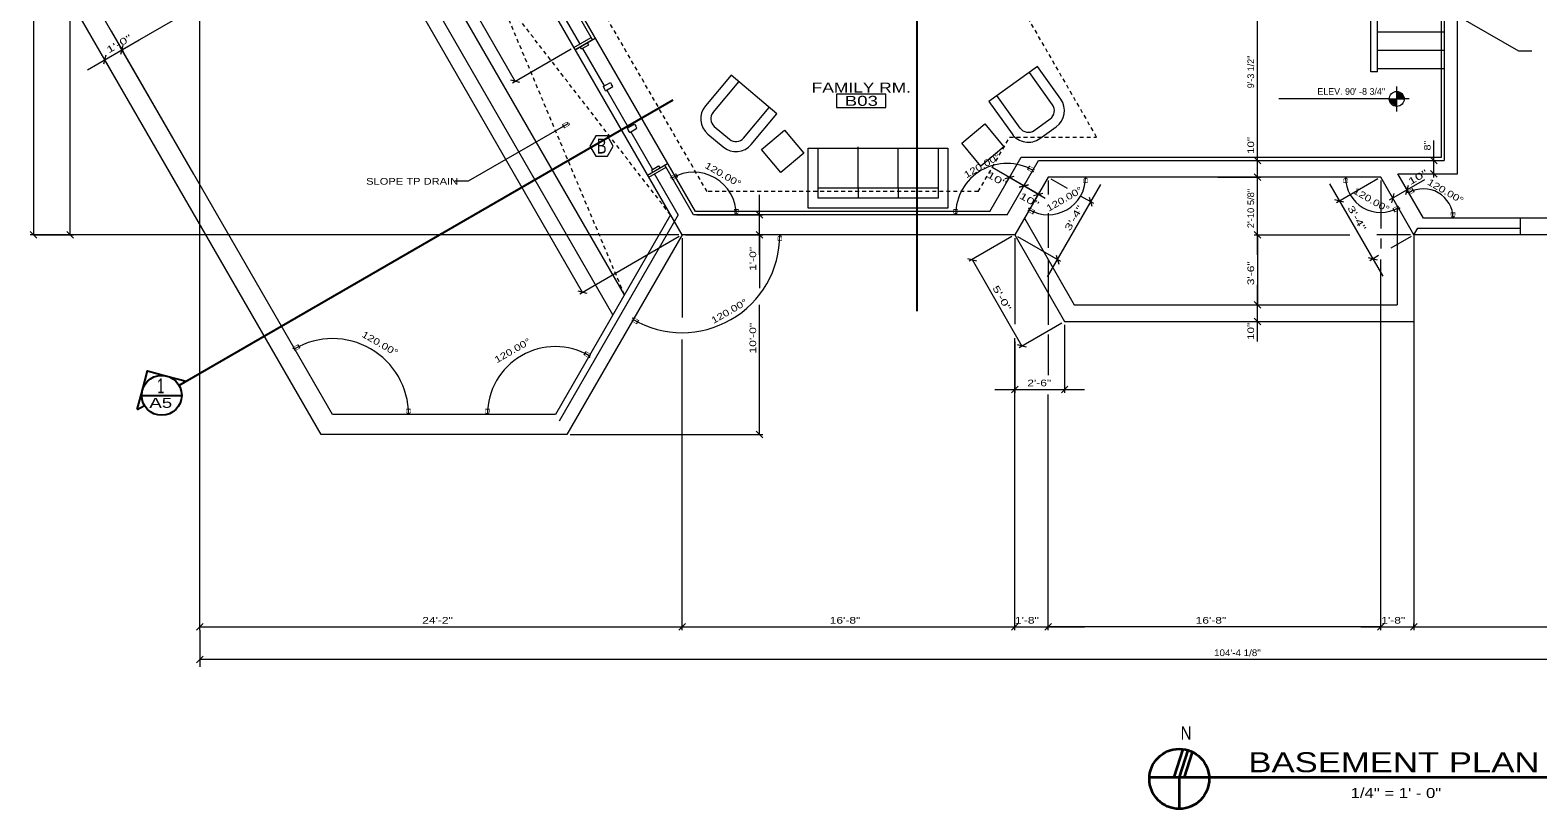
# Model space of a CAD drawing. Extents: x 7 to 126, y 6 to 93.
# Drawn here: x 8.2 to 83.7, y 5.6 to 44.6 of the extents above; entities that cross this region are included whole.
import ezdxf
from ezdxf.enums import TextEntityAlignment as Align

# ---------------------------------------------------------------- set-up
doc = ezdxf.new("R2010")
doc.units = 0
doc.header["$LTSCALE"] = 0.13
doc.linetypes.add('SHORT_DASHED', pattern=[2.7, 1.5, -1.2])
for name, color, linetype, lineweight in [('13', 7, 'Continuous', 13), ('14', 7, 'Continuous', 13), ('15', 7, 'Continuous', 13), ('16', 7, 'Continuous', 13), ('20', 7, 'Continuous', 13), ('22', 7, 'SHORT_DASHED', 13), ('24', 7, 'Continuous', 13), ('34', 7, 'Continuous', 13), ('4', 7, 'Continuous', 13), ('40', 7, 'Continuous', 13), ('42', 7, 'Continuous', 13), ('44', 7, 'Continuous', 13), ('45', 7, 'Continuous', 13), ('47', 7, 'Continuous', 35), ('50', 7, 'Continuous', 13), ('6', 7, 'SHORT_DASHED', 13), ('7', 7, 'Continuous', 13)]:
    doc.layers.add(name, color=color, linetype=linetype, lineweight=lineweight)

msp = doc.modelspace()

# ---------------------------------------------------------------- linework, layer by layer
at = {"layer": '13'}
for p, q in [((28.9778, 55.6199), (35.7268, 43.9303)), ((40.6799, 35.3511), (39.4914, 37.4098)), ((40.6799, 35.3511), (34.714, 25.0178)), ((77.539, 34.3511), (77.7315, 34.6845)), ((77.7315, 34.6845), (82.8724, 34.6845))]:
    msp.add_line(p, q, dxfattribs=at)
at = {"layer": '14'}
msp.add_lwpolyline([(115.8724, 34.3511), (77.539, 34.3511), (75.8724, 37.2379), (59.2057, 37.2379), (57.539, 34.3511), (40.8724, 34.3511), (16.7057, 76.209), (22.539, 86.3127), (34.2057, 86.3127), (44.2057, 68.9922), (60.8724, 68.9922)], dxfattribs=at)
at = {"layer": '15'}
for p, q in [((79.0473, 62.3853), (79.0473, 38.0712)), ((79.7139, 37.4046), (79.7139, 56.3207)), ((36.3842, 44.1248), (34.6032, 47.2098)), ((35.4556, 43.733), (36.3216, 44.233)), ((39.2056, 37.2378), (40.0716, 37.7378)), ((76.7384, 37.4046), (79.7139, 37.4046)), ((76.7057, 35.7945), (76.7057, 30.8544)), ((82.8724, 34.3511), (82.8724, 35.1845)), ((77.539, 34.3511), (77.539, 30.021))]:
    msp.add_line(p, q, dxfattribs=at)
for points in [[(57.1541, 35.3511), (41.4497, 35.3511), (40.0092, 37.8461)], [(57.1541, 35.3511), (58.7246, 38.0712), (79.0473, 38.0712)], [(115.258, 35.1845), (78.0202, 35.1845), (76.7384, 37.4046)], [(58.0202, 35.1845), (60.5202, 30.8544), (76.7057, 30.8544)], [(57.539, 34.3511), (60.039, 30.021), (77.539, 30.021)]]:
    msp.add_lwpolyline(points, dxfattribs=at)
at = {"layer": '16'}
for p, q in [((35.5181, 43.6248), (36.5157, 44.2008)), ((35.5542, 43.6456), (36.4203, 44.1456)), ((35.8332, 43.6624), (36.1941, 43.8707)), ((36.1941, 43.8707), (36.1339, 43.975)), ((35.8332, 43.6624), (35.773, 43.7667)), ((35.8874, 43.6936), (36.9754, 41.809)), ((36.9213, 41.7778), (37.2821, 41.9861)), ((36.9213, 41.7778), (36.9815, 41.6735)), ((37.0417, 41.5692), (36.9815, 41.6735)), ((37.0417, 41.5692), (37.4026, 41.7775)), ((37.0959, 41.6004), (38.1813, 39.7204)), ((37.2821, 41.9861), (37.3423, 41.8818)), ((37.4026, 41.7775), (37.3423, 41.8818)), ((38.1272, 39.6891), (38.488, 39.8974)), ((38.1272, 39.6891), (38.1874, 39.5848)), ((38.2476, 39.4805), (38.1874, 39.5848)), ((38.2476, 39.4805), (38.6085, 39.6888)), ((38.3017, 39.5118), (39.3874, 37.6314)), ((38.488, 39.8974), (38.5482, 39.7931)), ((38.6085, 39.6888), (38.5482, 39.7931)), ((39.1431, 37.3461), (40.1408, 37.9221)), ((39.1792, 37.3669), (40.0452, 37.8669)), ((39.3332, 37.6002), (39.6941, 37.8085)), ((39.6941, 37.8085), (39.7543, 37.7042)), ((39.3332, 37.6002), (39.3934, 37.4959))]:
    msp.add_line(p, q, dxfattribs=at)
at = {"layer": '20'}
for p, q in [((75.7139, 44.5146), (79.0473, 44.5146)), ((75.7139, 43.5979), (79.0473, 43.5979)), ((75.7139, 42.6813), (79.0473, 42.6813))]:
    msp.add_line(p, q, dxfattribs=at)
at = {"layer": '22'}
msp.add_line((55.0345, 50.6771), (61.6389, 39.2379), dxfattribs=at)
for points in [[(55.7108, 36.5178), (42.1233, 36.5178), (28.8321, 59.5389)], [(55.7108, 36.5178), (57.2812, 39.2379), (61.6389, 39.2379)]]:
    msp.add_lwpolyline(points, dxfattribs=at)
at = {"layer": '24'}
for p, q in [((78.9223, 38.2379), (78.9223, 56.4583)), ((75.7139, 42.5146), (75.7139, 47.375)), ((56.2881, 35.5178), (57.8586, 38.2379)), ((57.8586, 38.2379), (78.9223, 38.2379))]:
    msp.add_line(p, q, dxfattribs=at)
for points in [[(56.2881, 35.5178), (41.5459, 35.5178), (29.6995, 56.0365)], [(75.7139, 42.5146), (75.3806, 42.5146), (75.3806, 47.375)]]:
    msp.add_lwpolyline(points, dxfattribs=at)
at = {"layer": '34'}
for p, q in [((59.4352, 40.8627), (58.2727, 42.4902)), ((42.4223, 40.4888), (43.7081, 42.0206)), ((57.8077, 39.7002), (56.6453, 41.3277)), ((43.9541, 39.2029), (45.24, 40.7347)), ((58.5052, 39.584), (59.319, 40.1652)), ((42.1623, 39.4014), (42.9282, 38.7584)), ((42.4838, 39.7843), (43.2497, 39.1414)), ((58.7959, 39.1771), (59.6096, 39.7583)), ((49.6935, 36.6904), (49.6934, 38.7574)), ((51.6935, 36.6904), (51.6934, 38.7049)), ((53.6934, 36.6904), (47.6934, 36.6904)), ((49.6935, 36.6904), (49.6935, 36.2036)), ((51.6935, 36.6904), (51.6934, 36.1896))]:
    msp.add_line(p, q, dxfattribs=at)
for points in [[(44.3371, 38.8814), (45.6229, 40.4133), (43.3252, 42.3421), (42.0393, 40.8102)], [(59.8421, 41.1533), (58.6796, 42.7808), (56.2384, 41.0371), (57.4009, 39.4096)], [(53.6934, 38.6904), (53.6934, 36.1905), (47.6934, 36.1904), (47.6934, 38.6904)]]:
    msp.add_lwpolyline(points, dxfattribs=at)
for points in [[(46.97, 38.4414), (45.8177, 37.4811), (44.8574, 38.6335), (46.0097, 39.5937)], [(56.9948, 38.7579), (55.8425, 37.7976), (54.8822, 38.9499), (56.0346, 39.9102)], [(54.1934, 35.6904), (47.1934, 35.6904), (47.1934, 38.6904), (54.1934, 38.6905)]]:
    msp.add_lwpolyline(points, close=True, dxfattribs=at)
for centre, radius, start, end in [((42.8052, 40.1673), 1, 139.98937, 229.98937), ((59.0284, 40.5721), 0.5, 305.5378, 35.5378), ((59.0284, 40.5721), 1, 305.5378, 35.5378), ((42.8052, 40.1673), 0.5, 139.98937, 229.98937), ((58.2146, 39.9908), 1, 215.5378, 305.5378), ((58.2146, 39.9908), 0.5, 215.5378, 305.5378), ((43.5712, 39.5244), 1, 229.98937, 319.98937), ((43.5712, 39.5244), 0.5, 229.98937, 319.98937)]:
    msp.add_arc(centre, radius, start, end, dxfattribs=at)
at = {"layer": '4'}
for p, q in [((37.9856, 31.3511), (15.2614, 70.7105)), ((37.4082, 30.3511), (15.5393, 68.2293)), ((23.3594, 25.3511), (9.6233, 49.1428)), ((22.7821, 24.3511), (8.5387, 49.0213)), ((40.295, 35.3511), (34.5215, 25.3511)), ((40.8724, 34.3511), (35.0989, 24.3511)), ((34.5215, 25.3511), (23.3594, 25.3511)), ((35.0989, 24.3511), (22.7821, 24.3511))]:
    msp.add_line(p, q, dxfattribs=at)
at = {"layer": '40', "lineweight": 25}
for p, q in [((52.6458, 30.5373), (52.6458, 54.1771)), ((15.6657, 26.8165), (40.4229, 41.1101)), ((15.0585, 27.2824), (16.0244, 27.0236)), ((13.5749, 25.6094), (13.8337, 26.5753)), ((15.6657, 26.8165), (16.0244, 27.0236)), ((13.5749, 25.6094), (13.9336, 25.8165)), ((13.7996, 26.3165), (15.7996, 26.3165))]:
    msp.add_line(p, q, dxfattribs=at)
msp.add_lwpolyline([(13.8337, 26.5753), (14.0925, 27.5412), (15.0585, 27.2824)], dxfattribs=at)
msp.add_circle((14.7996, 26.3165), 1, dxfattribs=at)
at = {"layer": '42'}
msp.add_lwpolyline([(37.4229, 38.8023), (37.1312, 39.3074), (36.5479, 39.3074), (36.2562, 38.8023), (36.5479, 38.2971), (37.1312, 38.2971)], close=True, dxfattribs=at)
at = {"layer": '44'}
for p, q in [((76.6783, 41.5342), (76.6783, 41.7842)), ((76.3033, 41.1594), (70.7616, 41.1594)), ((76.3036, 41.1594), (76.0536, 41.1594)), ((76.6783, 41.1594), (76.3049, 41.1296)), ((76.6783, 41.1594), (76.3113, 41.083)), ((76.6783, 41.1594), (76.323, 41.0401)), ((76.6783, 41.1594), (76.3395, 40.9995)), ((76.6783, 41.1594), (76.3657, 40.9532)), ((76.6783, 41.1594), (76.3977, 40.911)), ((76.6783, 41.1594), (76.4368, 40.8732)), ((76.6783, 41.1594), (76.4899, 40.8353)), ((76.6783, 41.1594), (76.5403, 40.8167)), ((76.6783, 41.1594), (76.6103, 40.7911)), ((76.6783, 41.1594), (76.7263, 41.531)), ((76.6783, 41.1594), (76.7837, 41.5189)), ((76.6783, 41.1594), (76.8252, 41.5042)), ((76.6783, 41.1594), (76.8761, 41.4775)), ((76.6783, 41.1594), (76.9247, 41.4418)), ((76.6783, 41.1594), (76.9588, 41.4081)), ((76.6783, 41.1594), (76.9852, 41.3745)), ((76.6783, 41.1594), (77.0079, 41.3374)), ((76.6783, 41.1594), (77.0237, 41.3047)), ((76.6783, 41.1594), (77.0365, 41.2694)), ((76.6783, 41.1594), (77.045, 41.2381)), ((76.6783, 41.1594), (77.0508, 41.2014)), ((76.6783, 41.1594), (77.0531, 41.1594)), ((76.6783, 40.7847), (76.6783, 41.1594)), ((77.3031, 41.1594), (77.0531, 41.1594)), ((76.6783, 40.5347), (76.6783, 40.7847))]:
    msp.add_line(p, q, dxfattribs=at)
msp.add_lwpolyline([(76.3036, 41.1594), (76.6783, 41.1594), (76.6783, 41.5342)], dxfattribs=at)
msp.add_circle((76.6783, 41.1594), 0.375, dxfattribs=at)
at = {"layer": '45'}
msp.add_lwpolyline([(48.6026, 40.7271), (51.0878, 40.7271), (51.0878, 41.3977), (48.6026, 41.3977)], close=True, dxfattribs=at)
at = {"layer": '47'}
for p, q in [((65.5261, 7.195), (65.973, 8.5995)), ((65.7885, 7.195), (66.2187, 8.5469)), ((66.0508, 7.195), (66.4515, 8.4543)), ((64.285, 7.195), (84.1994, 7.195)), ((65.7827, 7.195), (65.7827, 5.6116))]:
    msp.add_line(p, q, dxfattribs=at)
msp.add_circle((65.7827, 7.1116), 1.5, dxfattribs=at)
at = {"layer": '50'}
for p, q in [((8.375, 86.3127), (8.375, 34.3511)), ((35.8878, 31.4733), (18.5561, 61.4926)), ((10.2188, 34.3511), (10.2188, 57.2579)), ((16.7057, 14.5521), (16.7057, 56.3333)), ((27.0989, 51.4175), (32.5155, 42.0356)), ((12.8094, 43.6243), (25.5111, 50.9576)), ((69.6979, 38.0712), (69.6979, 47.3596)), ((11.0773, 42.6243), (13.6754, 44.1243)), ((12.2692, 44.56), (12.8927, 43.48)), ((12.7484, 43.3966), (12.8704, 43.852)), ((12.7484, 43.3966), (12.8704, 43.852)), ((12.7484, 43.3966), (12.8704, 43.852)), ((15.5771, 36.8306), (11.86, 43.2686)), ((12.0044, 43.352), (11.8824, 42.8966)), ((16.408, 37.3913), (12.7261, 43.7686)), ((35.3113, 43.6497), (32.3712, 41.9522)), ((32.7432, 41.9746), (32.2879, 42.0966)), ((69.6979, 36.2379), (69.6979, 39.0712)), ((78.5417, 37.2188), (78.5417, 39.0729)), ((69.0526, 38.0712), (69.8646, 38.0712)), ((69.8646, 37.9046), (69.5312, 38.2379)), ((69.8646, 37.9046), (69.5312, 38.2379)), ((69.6979, 33.3511), (69.6979, 38.2379)), ((78.7083, 37.9062), (78.375, 38.2396)), ((78.5938, 38.0729), (78.7083, 38.0729)), ((58.8582, 36.3026), (56.4045, 37.7193)), ((57.4981, 37.2803), (57.0428, 37.1583)), ((59.0677, 36.1817), (57.1261, 37.3026)), ((57.1741, 37.0523), (57.3538, 37.3637)), ((59.2057, 37.0712), (59.2057, 36.375)), ((59.35, 37.1546), (60.1594, 36.6873)), ((67.7057, 37.2379), (69.8646, 37.2379)), ((69.8646, 37.0712), (69.5312, 37.4046)), ((69.5312, 37.4046), (69.8646, 37.0712)), ((75.728, 37.1546), (73.661, 35.9611)), ((75.8724, 37.0712), (75.8724, 34.6771)), ((78.0653, 37.1063), (76.3041, 36.0895)), ((78.375, 37.5712), (78.7083, 37.2379)), ((78.3928, 37.4046), (78.7083, 37.4046)), ((44.75, 33.3511), (44.75, 36.3511)), ((57.7645, 36.7416), (58.2198, 36.8636)), ((58.2198, 36.8636), (57.7645, 36.7416)), ((58.0401, 36.8856), (58.0755, 36.947)), ((58.4731, 35.969), (58.7972, 36.5303)), ((58.4862, 36.325), (58.9415, 36.447)), ((59.1816, 32.2481), (61.8483, 36.8669)), ((61.4926, 35.9175), (60.8658, 36.2794)), ((73.3053, 36.9105), (75.972, 32.2917)), ((76.6337, 35.9193), (76.3942, 36.334)), ((76.5386, 36.4173), (76.4166, 35.962)), ((77.295, 36.4404), (77.1159, 36.7506)), ((77.1383, 36.3786), (77.2603, 36.834)), ((44.9167, 35.1845), (44.5833, 35.5178)), ((61.4093, 35.7732), (61.2873, 36.2285)), ((74.033, 35.9835), (73.5776, 36.1055)), ((41.6164, 35.3511), (44.9167, 35.3511)), ((59.2057, 35.4479), (59.2057, 33.7083)), ((8.5417, 34.1845), (8.2083, 34.5178)), ((40.7057, 34.3511), (8.2083, 34.3511)), ((8.375, 34.3511), (10.3854, 34.3511)), ((10.3854, 34.1845), (10.0521, 34.5178)), ((40.728, 34.2678), (35.7434, 31.3899)), ((40.8724, 34.1845), (40.8724, 30.2083)), ((41.039, 34.3511), (44.9167, 34.3511)), ((44.5833, 34.5178), (44.9167, 34.1845)), ((44.5833, 34.5178), (44.9167, 34.1845)), ((44.75, 34.3511), (44.75, 31.6875)), ((57.3947, 34.2678), (55.254, 33.0319)), ((57.539, 34.1845), (57.539, 29.8854)), ((57.6834, 34.2678), (59.826, 33.0308)), ((69.8646, 34.1845), (69.5312, 34.5178)), ((69.5312, 34.5178), (69.8646, 34.1845)), ((69.5312, 34.5178), (69.8646, 34.1845)), ((69.5312, 34.3511), (74.3333, 34.3511)), ((69.6979, 34.3511), (69.6979, 30.8544)), ((69.6979, 34.3511), (69.8646, 34.3511)), ((77.3724, 34.3511), (75.6875, 34.3511)), ((75.8724, 34.1667), (75.8724, 33.6667)), ((77.3947, 34.2678), (76.3776, 33.6806)), ((77.539, 34.1845), (77.539, 14.5521)), ((59.6206, 33.3418), (59.7426, 32.8864)), ((75.3276, 33.0744), (75.7709, 33.3303)), ((55.1707, 33.1762), (55.626, 33.0542)), ((55.3984, 33.1152), (57.8984, 28.7851)), ((59.2057, 33.0938), (59.2057, 29.8438)), ((75.2443, 33.2187), (75.6996, 33.0967)), ((75.8724, 14.5521), (75.8724, 33.125)), ((69.6979, 29.021), (69.6979, 31.8544)), ((36.1154, 31.4123), (35.6601, 31.5343)), ((69.8646, 30.6877), (69.5312, 31.021)), ((69.8646, 30.6877), (69.5312, 31.021)), ((44.75, 24.3511), (44.75, 30.8542)), ((68.7796, 30.8544), (69.8646, 30.8544)), ((59.8947, 29.9377), (57.754, 28.7018)), ((60.039, 29.8544), (60.039, 26.4375)), ((68.9557, 30.021), (69.8646, 30.021)), ((69.5312, 30.1877), (69.8646, 29.8544)), ((40.8724, 14.5521), (40.8724, 29.1146)), ((57.539, 14.5521), (57.539, 29.1875)), ((57.539, 29.0208), (57.539, 26.4375)), ((58.126, 28.7241), (57.6707, 28.8461)), ((59.2057, 29.3698), (59.2057, 27.3333)), ((56.539, 26.6042), (61.039, 26.6042)), ((57.7057, 26.7708), (57.3724, 26.4375)), ((59.8724, 26.4375), (60.2057, 26.7708)), ((59.2057, 14.5521), (59.2057, 26.3646)), ((35.2655, 24.3511), (44.9167, 24.3511)), ((44.9167, 24.1845), (44.5833, 24.5178)), ((16.539, 14.5521), (16.8724, 14.8854)), ((16.7057, 14.7188), (40.8724, 14.7188)), ((16.7057, 14.5521), (16.7057, 12.7188)), ((41.039, 14.8854), (40.7057, 14.5521)), ((40.7057, 14.5521), (41.039, 14.8854)), ((40.8724, 14.7188), (61.039, 14.7188)), ((56.539, 14.7188), (60.2057, 14.7188)), ((57.7057, 14.8854), (57.3724, 14.5521)), ((57.7057, 14.8854), (57.3724, 14.5521)), ((57.7057, 14.8854), (57.3724, 14.5521)), ((57.539, 14.7188), (57.539, 14.8854)), ((59.039, 14.5521), (59.3724, 14.8854)), ((59.039, 14.5521), (59.3724, 14.8854)), ((75.8724, 14.7188), (59.2057, 14.7188)), ((74.8724, 14.7188), (78.539, 14.7188)), ((76.039, 14.8854), (75.7057, 14.5521)), ((76.039, 14.8854), (75.7057, 14.5521)), ((77.3724, 14.5521), (77.7057, 14.8854)), ((77.3724, 14.5521), (77.7057, 14.8854)), ((77.3724, 14.5521), (77.7057, 14.8854)), ((77.539, 14.7188), (77.539, 14.8854)), ((77.539, 14.7188), (115.8724, 14.7188)), ((16.539, 12.9271), (16.8724, 13.2604)), ((16.7057, 13.4688), (16.7057, 12.9271)), ((121.0473, 13.0938), (16.7057, 13.0938))]:
    msp.add_line(p, q, dxfattribs=at)
for points in [[(77.4062, 46.6771), (82.7784, 43.5755), (83.4451, 43.5755)], [(35.1458, 39.9167), (30.1534, 37.0343), (29.4868, 37.0343)]]:
    msp.add_lwpolyline(points, dxfattribs=at)
for centre, radius, start, end in [((57.1541, 35.3511), 2.5802, 59.99997, 180), ((41.4497, 35.3511), 2.1384, 0, 119.99947), ((59.2057, 37.2379), 1.8804, 240.00002, 360), ((75.8724, 37.2379), 1.7622, 180, 300.00032), ((78.0202, 35.1845), 1.4771, 0, 119.9997), ((40.8724, 34.3511), 4.8961, 240.0001, 0), ((23.3594, 25.3511), 3.8058, 0, 119.99997), ((34.5215, 25.3511), 3.4038, 59.99988, 180)]:
    msp.add_arc(centre, radius, start, end, dxfattribs=at)
at = {"layer": '6'}
for p, q in [((37.9856, 31.3511), (31.6949, 46.3234)), ((40.295, 35.3511), (31.7616, 46.3759))]:
    msp.add_line(p, q, dxfattribs=at)
at = {"layer": '7'}
msp.add_lwpolyline([(115.8724, 34.3511), (77.539, 34.3511), (75.8724, 37.2379), (59.2057, 37.2379), (57.539, 34.3511), (40.8724, 34.3511), (16.7057, 76.209), (22.539, 86.3127), (34.2057, 86.3127), (44.2057, 68.9922), (60.8724, 68.9922), (64.2057, 63.2187), (65.039, 63.2187), (75.039, 63.2187), (80.039, 71.8789), (96.7057, 71.8789), (98.789, 75.4873), (113.4884, 75.4873), (121.0473, 51.0685)], dxfattribs=at)

# ---------------------------------------------------------------- texts
at = {"layer": '40'}
for s, height, width, p in [('1', 0.75, 0.65, (14.7559, 26.4175)), ('A5 ', 0.5, 1.4, (14.8819, 25.6915))]:
    msp.add_text(s, height=height, dxfattribs=dict(at, width=width)).set_placement(p, align=Align.CENTER)
at = {"layer": '42', "width": 0.75}
msp.add_text('B', height=0.75, dxfattribs=at).set_placement((36.8396, 38.4273), align=Align.CENTER)
at = {"layer": '44'}
msp.add_text('ELEV. 90\' -8 3/4"', height=0.3333, dxfattribs=at).set_placement((72.6991, 41.3678))
at = {"layer": '45'}
for s, width, p in [('     FAMILY RM.     ', 1.3, (49.8526, 41.481)), (' B03 ', 1.4, (49.8526, 40.8144))]:
    msp.add_text(s, height=0.5, dxfattribs=dict(at, width=width)).set_placement(p, align=Align.CENTER)
at = {"layer": '47'}
for s, height, width, p in [('N', 0.6667, 0.85, (65.8481, 9.0793)), ('BASEMENT PLAN', 1, 1.3, (69.241, 7.445)), ('1/4" = 1\' - 0"', 0.5, 1.25, (74.366, 6.1533))]:
    msp.add_text(s, height=height, dxfattribs=dict(at, width=width)).set_placement(p)
at = {"layer": '50'}
for s, rotation, width, p in [('1\'-0"', 30, 1.55, (12.1487, 43.4353)), ('10"', 90, 1.3, (69.5312, 38.4046)), ('8"', 90, 1.2, (78.375, 38.5786)), ('120.00°', 330, 1.3, (41.9753, 37.7303)), ('120.00°', 30, 1.3, (55.1146, 37.178)), ('10"', 330, 1.6, (56.1039, 37.269)), ('10"', 30, 1.6, (77.3612, 36.8409)), ('120.00°', 330, 1.3, (78.1725, 36.8979)), ('10"', 330, 1.6, (57.729, 36.2159)), ('120.00°', 30, 1.3, (59.2377, 35.5054)), ('2\'-10 5/8"', 90, 1.05, (69.5312, 34.6848)), ('120.00°', 330, 1.3, (74.457, 36.4552)), ('3\'-4"', 60, 1.55, (60.2996, 34.5178)), ('3\'-4"', 300, 1.55, (74.1932, 35.7059)), ('1\'-0"', 90, 1.35, (44.5833, 32.5511)), ('3\'-6"', 90, 1.35, (69.5312, 31.8311)), ('5\'-0"', 300, 1.55, (56.4069, 31.7018)), ('120.00°', 30, 1.3, (42.4498, 29.8896)), ('120.00°', 330, 1.3, (24.7861, 29.273)), ('10\'-0"', 90, 1.35, (44.5833, 28.4141)), ('10"', 90, 1.3, (69.5312, 29.0948)), ('120.00°', 30, 1.3, (31.5885, 27.9178))]:
    msp.add_text(s, height=0.3333, rotation=rotation, dxfattribs=dict(at, width=width)).set_placement(p)
msp.add_text('9\'-3 1/2"', height=0.3333, rotation=90, dxfattribs=at).set_placement((69.5312, 41.6944))
for rotation, width, p in [(30, 2.35, (35.3125, 39.8846)), (330, 2.35, (58.4998, 37.4253)), (209.999, 2.35, (40.2139, 37.2351)), (90, 1.7, (61.1972, 37.2379)), (90, 1.7, (74.2213, 37.2379)), (210, 2.35, (77.115, 36.4957)), (270, 1.7, (43.477, 35.3511)), (270, 1.7, (54.4628, 35.3511)), (150, 2.35, (58.2099, 35.7698)), (30, 2.35, (76.9201, 35.6797)), (270, 1.7, (79.3861, 35.1845)), (90, 1.7, (45.8796, 34.3511)), (150, 2.35, (38.3687, 30.2713)), (210, 2.35, (21.2899, 28.6791)), (330, 2.35, (36.279, 28.1386)), (270, 1.7, (27.0541, 25.3511)), (270, 1.7, (31.0066, 25.3511))]:
    msp.add_text('B', height=0.2222, rotation=rotation, dxfattribs=dict(at, width=width)).set_placement(p, align=Align.RIGHT)
for s, width, p in [('SLOPE TP DRAIN', 1.25, (25.0414, 36.8676)), ('2\'-6"', 1.35, (58.1672, 26.7708)), ('24\'-2"', 1.35, (27.852, 14.8854)), ('16\'-8"', 1.35, (48.2687, 14.8854)), ('1\'-8"', 1.35, (57.5455, 14.8854)), ('16\'-8"', 1.35, (66.602, 14.8854)), ('1\'-8"', 1.35, (75.9036, 14.8854)), ('104\'-4 1/8"', 1.1, (67.5248, 13.2604))]:
    msp.add_text(s, height=0.3333, dxfattribs=dict(at, width=width)).set_placement(p)

doc.saveas('drawing.dxf')
